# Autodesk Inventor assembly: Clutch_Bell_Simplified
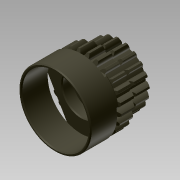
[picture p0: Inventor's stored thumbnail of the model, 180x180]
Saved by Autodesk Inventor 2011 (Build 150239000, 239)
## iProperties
Created: 2011-05
Part Number: Clutch_Bell_Simplified
Document SubType Name: Assembly
Designer: brillw
Author: brillw
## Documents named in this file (5)
- C:\Program Files\Autodesk\Inventor 2010\Samples\Clutch_Bell_Simplified\Clutch_Bell_Simplified.iam
- C:\Program Files\Autodesk\Inventor 2010\Samples\Clutch_Bell_Simplified\Copy of Clutch Bell.ipt
- C:\Program Files\Autodesk\Inventor 2010\Samples\Clutch_Bell_Simplified\Clutch Gear 25t.ipt
- C:\Program Files\Autodesk\Inventor 2010\Samples\Clutch_Bell_Simplified\Clutch Gear 20t.ipt
- C:\Program Files\Autodesk\Inventor 2010\Samples\Clutch_Bell_Simplified\STN 024630 - SKF 618_5.ipt
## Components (4 placed, 4 different names)
1. Copy of Clutch Bell:1 — Mate:1, Mate:2, Mate:4, Mate:5
2. Clutch Gear 25t:1 — Mate:1, Mate:2, Mate:3
3. Clutch Gear 20t:1 — Mate:3, Mate:4
4. STN 024630 SKF SKF 618/5:1 — Mate:5
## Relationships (5: Mate 5)
- Mate:1: Copy of Clutch Bell:1 ↔ Clutch Gear 25t:1
- Mate:2: Copy of Clutch Bell:1 ↔ Clutch Gear 25t:1
- Mate:3: Clutch Gear 25t:1 ↔ Clutch Gear 20t:1
- Mate:4: Copy of Clutch Bell:1 ↔ Clutch Gear 20t:1
- Mate:5: Copy of Clutch Bell:1 ↔ STN 024630 SKF SKF 618/5:1
